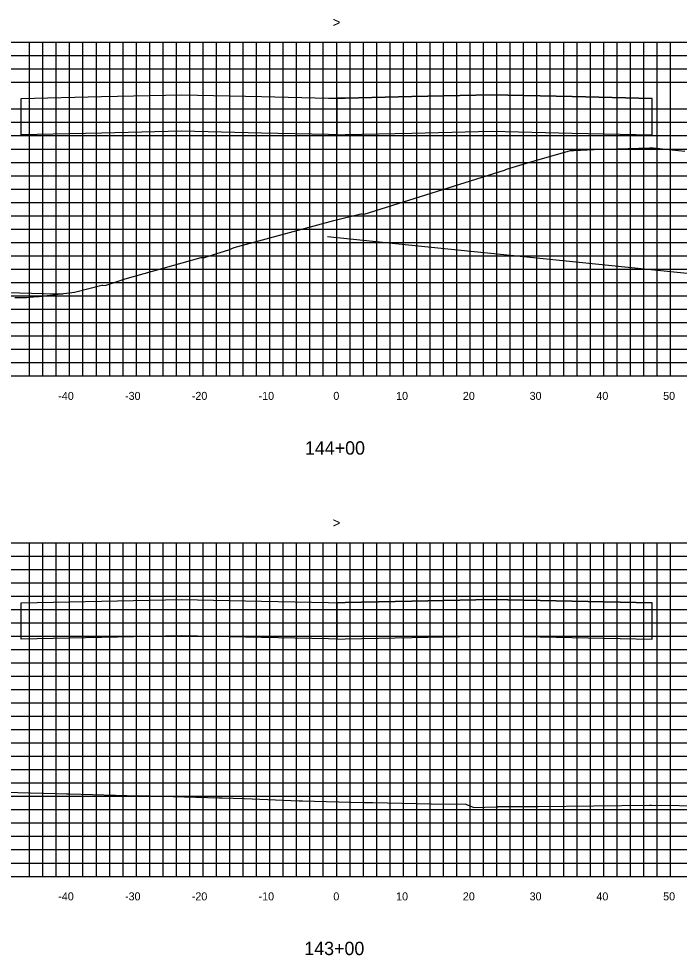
# Model space of a CAD drawing. Extents: x 1800880 to 1814006, y 250083 to 250560.
# Drawn here: x 1809383.4 to 1809482.3, y 250087.6 to 250228 of the extents above; entities that cross this region are included whole.
import ezdxf

# ---------------------------------------------------------------- set-up
doc = ezdxf.new("R2010")
doc.units = 0
for name, color, linetype in [('CL-CNST', 7, 'Continuous'), ('DESIGN - DRAINAGE - Bridges', 7, 'Continuous'), ('Level 32', 7, 'Continuous'), ('Level 46', 7, 'Continuous'), ('Level 62', 7, 'Continuous'), ('TOPO', 7, 'Continuous')]:
    doc.layers.add(name, color=color, linetype=linetype)

msp = doc.modelspace()

# ---------------------------------------------------------------- linework, layer by layer
at = {"layer": 'CL-CNST'}
for points in [[(1809382.81, 250186.18), (1809384.54, 250186.19), (1809386.16, 250186.32), (1809386.45, 250186.32), (1809391.71, 250186.96), (1809395.81, 250188.01), (1809395.95, 250188.01), (1809396.34, 250188), (1809399.3, 250188.97), (1809410.68, 250192.17), (1809410.75, 250192.17), (1809411.19, 250192.15), (1809413.05, 250192.77), (1809414.86, 250193.3), (1809415.62, 250193.67), (1809430.57, 250197.74), (1809434.63, 250198.71), (1809434.77, 250198.7), (1809435.12, 250198.68), (1809456.15, 250205.26), (1809456.42, 250205.39), (1809459.42, 250206.29), (1809460.26, 250206.57), (1809466.04, 250208.2), (1809466.52, 250208.2), (1809470.56, 250208.4), (1809471.47, 250208.43), (1809477.85, 250208.61), (1809477.91, 250208.61), (1809478.16, 250208.61), (1809478.4, 250208.61), (1809483.16, 250208.09)], [(1809381.31, 250112.05), (1809387.07, 250111.89), (1809390.51, 250111.8), (1809390.97, 250111.8), (1809401.32, 250111.52), (1809401.36, 250111.52), (1809401.8, 250111.52), (1809403.08, 250111.49), (1809413.37, 250111.19), (1809413.48, 250111.19), (1809413.85, 250111.19), (1809417.12, 250111.1), (1809425.39, 250110.77), (1809425.61, 250110.77), (1809425.88, 250110.77), (1809434.93, 250110.51), (1809435.95, 250110.48), (1809436.43, 250110.48), (1809445.14, 250110.3), (1809450.35, 250110.24), (1809450.94, 250110), (1809451.52, 250109.75), (1809453.2, 250109.78), (1809455.15, 250109.87), (1809455.2, 250109.89), (1809459.84, 250109.88), (1809459.99, 250109.88), (1809461.17, 250109.89), (1809477.87, 250110.12), (1809478.15, 250110.12), (1809486.5, 250110.02)]]:
    msp.add_lwpolyline(points, dxfattribs=at)
at = {"layer": 'DESIGN - DRAINAGE - Bridges'}
for p, q in [((1809281, 250174.43), (1809581, 250174.43)), ((1809391, 250174.37), (1809391, 250174.43)), ((1809401, 250174.37), (1809401, 250174.43)), ((1809411, 250174.37), (1809411, 250174.43)), ((1809421, 250174.37), (1809421, 250174.43)), ((1809431, 250174.37), (1809431, 250174.43)), ((1809441, 250174.37), (1809441, 250174.43)), ((1809451, 250174.37), (1809451, 250174.43)), ((1809461, 250174.37), (1809461, 250174.43)), ((1809471, 250174.37), (1809471, 250174.43)), ((1809481, 250174.37), (1809481, 250174.43)), ((1809281, 250099.43), (1809581, 250099.43)), ((1809391, 250099.37), (1809391, 250099.43)), ((1809401, 250099.37), (1809401, 250099.43)), ((1809411, 250099.37), (1809411, 250099.43)), ((1809421, 250099.37), (1809421, 250099.43)), ((1809431, 250099.37), (1809431, 250099.43)), ((1809441, 250099.37), (1809441, 250099.43)), ((1809451, 250099.37), (1809451, 250099.43)), ((1809461, 250099.37), (1809461, 250099.43)), ((1809471, 250099.37), (1809471, 250099.43)), ((1809481, 250099.37), (1809481, 250099.43))]:
    msp.add_line(p, q, dxfattribs=at)
at = {"layer": 'Level 46'}
for p, q in [((1809281, 250224.43), (1809581, 250224.43)), ((1809385, 250174.43), (1809385, 250224.43)), ((1809387, 250174.43), (1809387, 250224.43)), ((1809389, 250174.43), (1809389, 250224.43)), ((1809391, 250174.43), (1809391, 250224.43)), ((1809393, 250174.43), (1809393, 250224.43)), ((1809395, 250174.43), (1809395, 250224.43)), ((1809397, 250174.43), (1809397, 250224.43)), ((1809399, 250174.43), (1809399, 250224.43)), ((1809401, 250174.43), (1809401, 250224.43)), ((1809403, 250174.43), (1809403, 250224.43)), ((1809405, 250174.43), (1809405, 250224.43)), ((1809407, 250174.43), (1809407, 250224.43)), ((1809409, 250174.43), (1809409, 250224.43)), ((1809411, 250174.43), (1809411, 250224.43)), ((1809413, 250174.43), (1809413, 250224.43)), ((1809415, 250174.43), (1809415, 250224.43)), ((1809417, 250174.43), (1809417, 250224.43)), ((1809419, 250174.43), (1809419, 250224.43)), ((1809421, 250174.43), (1809421, 250224.43)), ((1809423, 250174.43), (1809423, 250224.43)), ((1809425, 250174.43), (1809425, 250224.43)), ((1809427, 250174.43), (1809427, 250224.43)), ((1809429, 250174.43), (1809429, 250224.43)), ((1809431, 250174.43), (1809431, 250224.43)), ((1809433, 250174.43), (1809433, 250224.43)), ((1809435, 250174.43), (1809435, 250224.43)), ((1809437, 250174.43), (1809437, 250224.43)), ((1809439, 250174.43), (1809439, 250224.43)), ((1809441, 250174.43), (1809441, 250224.43)), ((1809443, 250174.43), (1809443, 250224.43)), ((1809445, 250174.43), (1809445, 250224.43)), ((1809447, 250174.43), (1809447, 250224.43)), ((1809449, 250174.43), (1809449, 250224.43)), ((1809451, 250174.43), (1809451, 250224.43)), ((1809453, 250174.43), (1809453, 250224.43)), ((1809455, 250174.43), (1809455, 250224.43)), ((1809457, 250174.43), (1809457, 250224.43)), ((1809459, 250174.43), (1809459, 250224.43)), ((1809461, 250174.43), (1809461, 250224.43)), ((1809463, 250174.43), (1809463, 250224.43)), ((1809465, 250174.43), (1809465, 250224.43)), ((1809467, 250174.43), (1809467, 250224.43)), ((1809469, 250174.43), (1809469, 250224.43)), ((1809471, 250174.43), (1809471, 250224.43)), ((1809473, 250174.43), (1809473, 250224.43)), ((1809475, 250174.43), (1809475, 250224.43)), ((1809477, 250174.43), (1809477, 250224.43)), ((1809479, 250174.43), (1809479, 250224.43)), ((1809481, 250174.43), (1809481, 250224.43)), ((1809281, 250222.43), (1809581, 250222.43)), ((1809281, 250220.43), (1809581, 250220.43)), ((1809281, 250218.43), (1809581, 250218.43)), ((1809281, 250214.43), (1809581, 250214.43)), ((1809281, 250212.43), (1809581, 250212.43)), ((1809281, 250210.43), (1809581, 250210.43)), ((1809281, 250208.43), (1809581, 250208.43)), ((1809281, 250206.43), (1809581, 250206.43)), ((1809281, 250204.43), (1809581, 250204.43)), ((1809281, 250202.43), (1809581, 250202.43)), ((1809281, 250200.43), (1809581, 250200.43)), ((1809281, 250198.43), (1809581, 250198.43)), ((1809281, 250196.43), (1809581, 250196.43)), ((1809281, 250194.43), (1809581, 250194.43)), ((1809281, 250192.43), (1809581, 250192.43)), ((1809281, 250190.43), (1809581, 250190.43)), ((1809281, 250188.43), (1809581, 250188.43)), ((1809281, 250186.43), (1809581, 250186.43)), ((1809281, 250184.43), (1809581, 250184.43)), ((1809281, 250182.43), (1809581, 250182.43)), ((1809281, 250180.43), (1809581, 250180.43)), ((1809281, 250178.43), (1809581, 250178.43)), ((1809281, 250176.43), (1809581, 250176.43)), ((1809281, 250174.43), (1809581, 250174.43)), ((1809281, 250149.43), (1809581, 250149.43)), ((1809385, 250099.43), (1809385, 250149.43)), ((1809387, 250099.43), (1809387, 250149.43)), ((1809389, 250099.43), (1809389, 250149.43)), ((1809391, 250099.43), (1809391, 250149.43)), ((1809393, 250099.43), (1809393, 250149.43)), ((1809395, 250099.43), (1809395, 250149.43)), ((1809397, 250099.43), (1809397, 250149.43)), ((1809399, 250099.43), (1809399, 250149.43)), ((1809401, 250099.43), (1809401, 250149.43)), ((1809403, 250099.43), (1809403, 250149.43)), ((1809405, 250099.43), (1809405, 250149.43)), ((1809407, 250099.43), (1809407, 250149.43)), ((1809409, 250099.43), (1809409, 250149.43)), ((1809411, 250099.43), (1809411, 250149.43)), ((1809413, 250099.43), (1809413, 250149.43)), ((1809415, 250099.43), (1809415, 250149.43)), ((1809417, 250099.43), (1809417, 250149.43)), ((1809419, 250099.43), (1809419, 250149.43)), ((1809421, 250099.43), (1809421, 250149.43)), ((1809423, 250099.43), (1809423, 250149.43)), ((1809425, 250099.43), (1809425, 250149.43)), ((1809427, 250099.43), (1809427, 250149.43)), ((1809429, 250099.43), (1809429, 250149.43)), ((1809431, 250099.43), (1809431, 250149.43)), ((1809433, 250099.43), (1809433, 250149.43)), ((1809435, 250099.43), (1809435, 250149.43)), ((1809437, 250099.43), (1809437, 250149.43)), ((1809439, 250099.43), (1809439, 250149.43)), ((1809441, 250099.43), (1809441, 250149.43)), ((1809443, 250099.43), (1809443, 250149.43)), ((1809445, 250099.43), (1809445, 250149.43)), ((1809447, 250099.43), (1809447, 250149.43)), ((1809449, 250099.43), (1809449, 250149.43)), ((1809451, 250099.43), (1809451, 250149.43)), ((1809453, 250099.43), (1809453, 250149.43)), ((1809455, 250099.43), (1809455, 250149.43)), ((1809457, 250099.43), (1809457, 250149.43)), ((1809459, 250099.43), (1809459, 250149.43)), ((1809461, 250099.43), (1809461, 250149.43)), ((1809463, 250099.43), (1809463, 250149.43)), ((1809465, 250099.43), (1809465, 250149.43)), ((1809467, 250099.43), (1809467, 250149.43)), ((1809469, 250099.43), (1809469, 250149.43)), ((1809471, 250099.43), (1809471, 250149.43)), ((1809473, 250099.43), (1809473, 250149.43)), ((1809475, 250099.43), (1809475, 250149.43)), ((1809477, 250099.43), (1809477, 250149.43)), ((1809479, 250099.43), (1809479, 250149.43)), ((1809481, 250099.43), (1809481, 250149.43)), ((1809281, 250147.43), (1809581, 250147.43)), ((1809281, 250145.43), (1809581, 250145.43)), ((1809281, 250143.43), (1809581, 250143.43)), ((1809281, 250141.43), (1809581, 250141.43)), ((1809281, 250139.43), (1809581, 250139.43)), ((1809281, 250137.43), (1809581, 250137.43)), ((1809281, 250135.43), (1809581, 250135.43)), ((1809281, 250133.43), (1809581, 250133.43)), ((1809281, 250131.43), (1809581, 250131.43)), ((1809281, 250129.43), (1809581, 250129.43)), ((1809281, 250127.43), (1809581, 250127.43)), ((1809281, 250125.43), (1809581, 250125.43)), ((1809281, 250123.43), (1809581, 250123.43)), ((1809281, 250121.43), (1809581, 250121.43)), ((1809281, 250119.43), (1809581, 250119.43)), ((1809281, 250117.43), (1809581, 250117.43)), ((1809281, 250115.43), (1809581, 250115.43)), ((1809281, 250113.43), (1809581, 250113.43)), ((1809281, 250111.43), (1809581, 250111.43)), ((1809281, 250109.43), (1809581, 250109.43)), ((1809281, 250107.43), (1809581, 250107.43)), ((1809281, 250105.43), (1809581, 250105.43)), ((1809281, 250103.43), (1809581, 250103.43)), ((1809281, 250101.43), (1809581, 250101.43)), ((1809281, 250099.43), (1809581, 250099.43))]:
    msp.add_line(p, q, dxfattribs=at)
at = {"layer": 'Level 62'}
for points in [[(1809383.75, 250216.02), (1809395.75, 250216.28), (1809407.75, 250216.55), (1809419.75, 250216.28), (1809429.75, 250216.06), (1809431, 250216.03), (1809431, 250216.03), (1809432.25, 250216.06), (1809442.25, 250216.28), (1809454.25, 250216.55), (1809466.25, 250216.28), (1809478.25, 250216.02)], [(1809429.6, 250195.3), (1809443.71, 250193.87), (1809457.04, 250192.51), (1809507.95, 250187.34), (1809508.29, 250187.34), (1809512.02, 250187.33), (1809513.06, 250187.5), (1809526.91, 250189.72), (1809533.3, 250190.76), (1809533.41, 250190.76), (1809535.31, 250190.83), (1809535.6, 250190.84), (1809539.33, 250190.91), (1809544.69, 250190.78), (1809563.43, 250190.3), (1809568.43, 250190.09), (1809571.46, 250189.96), (1809572.92, 250189.89), (1809573.47, 250189.87), (1809579.86, 250188.79), (1809581, 250188.59)], [(1809281, 250186.85), (1809308.05, 250187.14), (1809333.53, 250186.97), (1809335.81, 250186.98), (1809361.25, 250187.42), (1809363.56, 250187.43), (1809388.88, 250186.74), (1809389.98, 250186.75)], [(1809383.75, 250140.42), (1809395.75, 250140.68), (1809407.75, 250140.94), (1809419.75, 250140.68), (1809429.75, 250140.46), (1809431, 250140.43), (1809431, 250140.43), (1809432.25, 250140.46), (1809442.25, 250140.68), (1809454.25, 250140.94), (1809466.25, 250140.68), (1809478.25, 250140.42)]]:
    msp.add_lwpolyline(points, dxfattribs=at)
at = {"layer": 'TOPO'}
for points in [[(1809395.75, 250210.82), (1809383.75, 250210.56), (1809383.75, 250216.02), (1809395.75, 250216.28), (1809407.75, 250216.55), (1809419.75, 250216.28), (1809429.75, 250216.06), (1809431, 250216.03), (1809431, 250210.57), (1809429.75, 250210.6), (1809419.75, 250210.82), (1809407.75, 250211.09)], [(1809466.25, 250210.82), (1809478.25, 250210.56), (1809478.25, 250216.02), (1809466.25, 250216.28), (1809454.25, 250216.55), (1809442.25, 250216.28), (1809432.25, 250216.06), (1809431, 250216.03), (1809431, 250210.57), (1809432.25, 250210.6), (1809442.25, 250210.82), (1809454.25, 250211.09)], [(1809395.75, 250135.22), (1809383.75, 250134.96), (1809383.75, 250140.42), (1809395.75, 250140.68), (1809407.75, 250140.94), (1809419.75, 250140.68), (1809429.75, 250140.46), (1809431, 250140.43), (1809431, 250134.97), (1809429.75, 250135), (1809419.75, 250135.22), (1809407.75, 250135.48)], [(1809466.25, 250135.22), (1809478.25, 250134.96), (1809478.25, 250140.42), (1809466.25, 250140.68), (1809454.25, 250140.94), (1809442.25, 250140.68), (1809432.25, 250140.46), (1809431, 250140.43), (1809431, 250134.97), (1809432.25, 250135), (1809442.25, 250135.22), (1809454.25, 250135.48)]]:
    msp.add_lwpolyline(points, close=True, dxfattribs=at)

# ---------------------------------------------------------------- texts
for s, p in [('-40', (1809389.3, 250170.83)), ('-30', (1809399.3, 250170.83)), ('-20', (1809409.3, 250170.83)), ('-10', (1809419.3, 250170.83)), ('0', (1809430.5, 250170.83)), ('10', (1809439.9, 250170.83)), ('20', (1809449.9, 250170.83)), ('30', (1809459.9, 250170.83)), ('40', (1809469.9, 250170.83)), ('50', (1809479.9, 250170.83)), ('-40', (1809389.3, 250095.83)), ('-30', (1809399.3, 250095.83)), ('-20', (1809409.3, 250095.83)), ('-10', (1809419.3, 250095.83)), ('0', (1809430.5, 250095.83)), ('10', (1809439.9, 250095.83)), ('20', (1809449.9, 250095.83)), ('30', (1809459.9, 250095.83)), ('40', (1809469.9, 250095.83)), ('50', (1809479.9, 250095.83))]:
    msp.add_text(s, height=1.2).set_placement(p)
at = {"layer": 'DESIGN - DRAINAGE - Bridges'}
for p in [(1809430.39, 250226.68), (1809430.39, 250151.68)]:
    msp.add_text('>', height=1.5, dxfattribs=at).set_placement(p)
at = {"layer": 'Level 32'}
for s, p in [('144+00', (1809426.24, 250162.63)), ('143+00', (1809426.14, 250087.63))]:
    msp.add_text(s, height=2, dxfattribs=at).set_placement(p)

doc.saveas('drawing.dxf')
